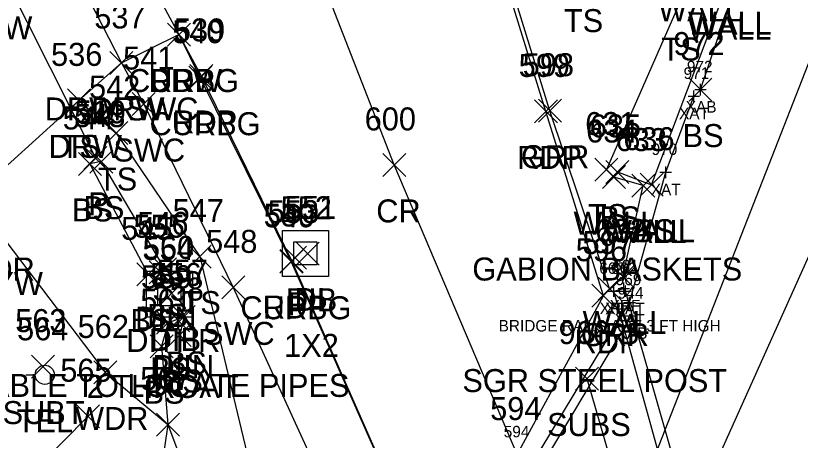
# Model space of a CAD drawing. Extents: x 1764889 to 1767296, y 695936 to 698960.
# Drawn here: x 1766282.3 to 1766350.6, y 696604 to 696640.9 of the extents above; entities that cross this region are included whole.
import ezdxf

# ---------------------------------------------------------------- set-up
doc = ezdxf.new("R2010")
doc.units = 0
for name, color, linetype in [('B_A', 7, 'Continuous'), ('B_C', 7, 'Continuous'), ('B_I', 7, 'Continuous'), ('B_TIC', 7, 'Continuous'), ('BF', 7, 'Continuous'), ('BR', 7, 'Continuous'), ('BSUBM', 7, 'Continuous'), ('D_A', 7, 'Continuous'), ('D_C', 7, 'Continuous'), ('D_I', 7, 'Continuous'), ('D_TIC', 7, 'Continuous'), ('DCP', 7, 'Continuous'), ('DS', 7, 'Continuous'), ('L_A', 7, 'Continuous'), ('L_C', 7, 'Continuous'), ('L_I', 7, 'Continuous'), ('L_TIC', 7, 'Continuous'), ('LAWA', 7, 'Continuous'), ('LELB', 7, 'Continuous'), ('LW', 7, 'Continuous'), ('P_A', 7, 'Continuous'), ('P_I', 7, 'Continuous'), ('P_TIC', 7, 'Continuous'), ('PET', 7, 'Continuous'), ('PRC', 7, 'Continuous'), ('R_A', 7, 'Continuous'), ('R_C', 7, 'Continuous'), ('R_I', 7, 'Continuous'), ('R_TIC', 7, 'Continuous'), ('RC', 7, 'Continuous'), ('RDW', 7, 'Continuous'), ('RGR', 7, 'Continuous'), ('RR', 7, 'Continuous'), ('RSW', 7, 'Continuous'), ('U_A', 7, 'Continuous'), ('U_I', 7, 'Continuous'), ('U_TIC', 7, 'Continuous'), ('UP', 7, 'Continuous'), ('USA', 7, 'Continuous')]:
    doc.layers.add(name, color=color, linetype=linetype)

msp = doc.modelspace()

# ---------------------------------------------------------------- linework, layer by layer
at = {"layer": 'B_TIC'}
for p, q in [((1766341.321, 696633.937), (1766341.396, 696633.937)), ((1766341.893, 696634.509), (1766341.968, 696634.509)), ((1766338.864, 696627.321), (1766338.94, 696627.321)), ((1766334.363, 696616.985), (1766334.438, 696616.985)), ((1766335.228, 696617.225), (1766335.303, 696617.225)), ((1766335.355, 696616.974), (1766335.431, 696616.974)), ((1766335.728, 696615.999), (1766335.803, 696615.999)), ((1766335.881, 696614.829), (1766335.956, 696614.829))]:
    msp.add_line(p, q, dxfattribs=at)
for points in [[(1766341.89, 696634.009), (1766341.89, 696635.009)], [(1766340.817, 696633.937), (1766341.817, 696633.937)], [(1766341.317, 696633.437), (1766341.317, 696634.437)], [(1766341.39, 696634.509), (1766342.39, 696634.509)], [(1766338.861, 696626.821), (1766338.861, 696627.821)], [(1766338.361, 696627.321), (1766339.361, 696627.321)], [(1766334.359, 696616.485), (1766334.359, 696617.485)], [(1766335.224, 696616.725), (1766335.224, 696617.725)], [(1766335.352, 696616.474), (1766335.352, 696617.474)], [(1766333.859, 696616.985), (1766334.859, 696616.985)], [(1766334.724, 696617.225), (1766335.724, 696617.225)], [(1766334.852, 696616.974), (1766335.852, 696616.974)], [(1766335.724, 696615.499), (1766335.724, 696616.499)], [(1766335.224, 696615.999), (1766336.224, 696615.999)], [(1766335.377, 696614.829), (1766336.377, 696614.829)], [(1766335.877, 696614.329), (1766335.877, 696615.329)]]:
    msp.add_lwpolyline(points, dxfattribs=at)
at = {"layer": 'BF'}
msp.add_lwpolyline([(1766346.637, 696577.566), (1766335.352, 696616.974)], dxfattribs=at)
at = {"layer": 'BR'}
msp.add_lwpolyline([(1766346.481, 696577.209), (1766345.386, 696577.081), (1766334.359, 696616.985), (1766335.224, 696617.225)], dxfattribs=at)
at = {"layer": 'BSUBM'}
for points in [[(1766308.079, 696576.128), (1766314.595, 696582.871), (1766317.47, 696585.8), (1766335.724, 696615.999), (1766338.861, 696627.321), (1766341.317, 696633.937)], [(1766301.191, 696567.632), (1766308.317, 696574.421), (1766317.361, 696583.898), (1766335.877, 696614.829)]]:
    msp.add_lwpolyline(points, dxfattribs=at)
at = {"layer": 'D_TIC'}
for points in [[(1766288.247, 696627.574), (1766290.247, 696629.574)], [(1766290.247, 696627.574), (1766288.247, 696629.574)], [(1766305.599, 696618.893), (1766307.599, 696620.893)], [(1766307.599, 696618.893), (1766305.599, 696620.893)], [(1766306.725, 696619.238), (1766308.725, 696621.238)], [(1766308.725, 696619.238), (1766306.725, 696621.238)], [(1766293.926, 696617.632), (1766295.926, 696619.632)], [(1766295.926, 696617.632), (1766293.926, 696619.632)], [(1766294.877, 696615.785), (1766296.877, 696617.785)], [(1766296.877, 696615.785), (1766294.877, 696617.785)], [(1766295.448, 696613.438), (1766297.448, 696615.438)], [(1766297.448, 696613.438), (1766295.448, 696615.438)]]:
    msp.add_lwpolyline(points, dxfattribs=at)
at = {"layer": 'DCP'}
msp.add_lwpolyline([(1766277.33, 696652.193), (1766289.247, 696628.574)], dxfattribs=at)
at = {"layer": 'DS'}
for p, q in [((1766305.518, 696622.266), (1766309.518, 696622.266)), ((1766305.518, 696618.266), (1766305.518, 696622.266)), ((1766309.518, 696622.266), (1766309.518, 696618.266)), ((1766306.518, 696619.266), (1766306.518, 696621.266)), ((1766306.518, 696621.266), (1766308.518, 696621.266)), ((1766308.518, 696621.266), (1766308.518, 696619.266)), ((1766307.523, 696620.268), (1766307.523, 696620.268)), ((1766307.523, 696620.268), (1766307.523, 696620.268)), ((1766308.518, 696619.266), (1766306.518, 696619.266)), ((1766293.687, 696618.718), (1766297.687, 696618.718)), ((1766293.687, 696614.718), (1766293.698, 696618.718)), ((1766297.687, 696618.718), (1766297.687, 696614.718)), ((1766309.518, 696618.266), (1766305.518, 696618.266)), ((1766294.687, 696617.718), (1766296.687, 696617.718)), ((1766294.687, 696615.718), (1766294.687, 696617.718)), ((1766296.687, 696617.718), (1766296.687, 696615.718)), ((1766295.69, 696616.728), (1766295.69, 696616.728)), ((1766296.687, 696615.718), (1766294.687, 696615.718)), ((1766297.687, 696614.718), (1766293.687, 696614.718)), ((1766296.187, 696614.718), (1766296.687, 696614.718))]:
    msp.add_line(p, q, dxfattribs=at)
at = {"layer": 'L_TIC'}
for points in [[(1766340.89, 696633.509), (1766342.89, 696635.509)], [(1766342.89, 696633.509), (1766340.89, 696635.509)], [(1766286.808, 696632.57), (1766288.808, 696634.57)], [(1766288.808, 696632.57), (1766286.808, 696634.57)], [(1766290.058, 696629.732), (1766292.058, 696631.732)], [(1766292.058, 696629.732), (1766290.058, 696631.732)], [(1766288.761, 696627.242), (1766290.761, 696629.242)], [(1766290.761, 696627.242), (1766288.761, 696629.242)], [(1766288.761, 696627.242), (1766290.761, 696629.242)], [(1766290.761, 696627.242), (1766288.761, 696629.242)], [(1766287.766, 696627.042), (1766289.766, 696629.042)], [(1766289.766, 696627.042), (1766287.766, 696629.042)], [(1766332.7, 696626.552), (1766334.7, 696628.552)], [(1766334.7, 696626.552), (1766332.7, 696628.552)], [(1766333.354, 696625.906), (1766335.354, 696627.906)], [(1766335.354, 696625.906), (1766333.354, 696627.906)], [(1766333.667, 696626.353), (1766335.667, 696628.353)], [(1766335.667, 696626.353), (1766333.667, 696628.353)], [(1766335.915, 696625.159), (1766337.915, 696627.159)], [(1766337.915, 696625.159), (1766335.915, 696627.159)], [(1766336.638, 696625.24), (1766338.638, 696627.24)], [(1766338.638, 696625.24), (1766336.638, 696627.24)], [(1766336.638, 696625.24), (1766338.638, 696627.24)], [(1766338.638, 696625.24), (1766336.638, 696627.24)], [(1766297.329, 696618.987), (1766299.329, 696620.987)], [(1766299.329, 696618.987), (1766297.329, 696620.987)], [(1766294.302, 696617.879), (1766296.302, 696619.879)], [(1766296.302, 696617.879), (1766294.302, 696619.879)], [(1766294.302, 696617.879), (1766296.302, 696619.879)], [(1766296.302, 696617.879), (1766294.302, 696619.879)], [(1766292.85, 696617.442), (1766294.85, 696619.442)], [(1766294.85, 696617.442), (1766292.85, 696619.442)], [(1766334.145, 696617.255), (1766336.145, 696619.255)], [(1766336.145, 696617.255), (1766334.145, 696619.255)], [(1766295.934, 696613.732), (1766297.934, 696615.732)], [(1766297.934, 696613.732), (1766295.934, 696615.732)], [(1766295.934, 696613.732), (1766297.934, 696615.732)], [(1766297.934, 696613.732), (1766295.934, 696615.732)], [(1766294.574, 696613.228), (1766296.574, 696615.228)], [(1766296.574, 696613.228), (1766294.574, 696615.228)], [(1766294.574, 696613.228), (1766296.574, 696615.228)], [(1766296.574, 696613.228), (1766294.574, 696615.228)], [(1766295.582, 696612.164), (1766297.582, 696614.164)], [(1766297.582, 696612.164), (1766295.582, 696614.164)], [(1766294, 696611.196), (1766296, 696613.196)], [(1766296, 696611.196), (1766294, 696613.196)], [(1766289.113, 696608.911), (1766291.113, 696610.911)], [(1766291.113, 696608.911), (1766289.113, 696610.911)], [(1766287.604, 696605.107), (1766289.604, 696607.107)], [(1766289.604, 696605.107), (1766287.604, 696607.107)], [(1766294.555, 696604.374), (1766296.555, 696606.374)], [(1766296.555, 696604.374), (1766294.555, 696606.374)], [(1766294.555, 696604.374), (1766296.555, 696606.374)], [(1766296.555, 696604.374), (1766294.555, 696606.374)]]:
    msp.add_lwpolyline(points, dxfattribs=at)
at = {"layer": 'LAWA'}
msp.add_lwpolyline([(1766267.506, 696602.037), (1766280.23, 696622.903), (1766290.113, 696609.911), (1766295.555, 696605.374), (1766300.13, 696593.204), (1766307.624, 696581.45)], dxfattribs=at)
at = {"layer": 'LELB'}
for points in [[(1766329.245, 696716.312), (1766323.358, 696694.495), (1766321.92, 696674.735), (1766323.815, 696657.808), (1766331.595, 696644.505), (1766340.076, 696642.034), (1766333.7, 696627.552)], [(1766311.883, 696556.718), (1766333.813, 696592.111), (1766361.339, 696662.502)], [(1766341.89, 696634.509), (1766349.453, 696656.955)], [(1766287.808, 696633.57), (1766291.058, 696630.732), (1766298.329, 696619.987), (1766303.91, 696596.744)], [(1766289.761, 696628.242), (1766288.766, 696628.042), (1766293.85, 696618.442), (1766295.302, 696618.879)], [(1766289.761, 696628.242), (1766295.302, 696618.879)], [(1766334.667, 696627.353), (1766337.638, 696626.24)], [(1766296.934, 696614.732), (1766296.582, 696613.164), (1766295.574, 696614.228), (1766295, 696612.196), (1766295.555, 696605.374), (1766294.049, 696594.976), (1766286.237, 696589.556)], [(1766296.934, 696614.732), (1766295.574, 696614.228)], [(1766288.604, 696606.107), (1766277.65, 696595.052)]]:
    msp.add_lwpolyline(points, dxfattribs=at)
at = {"layer": 'LW'}
for points in [[(1766337.638, 696626.24), (1766344.295, 696643.864), (1766339.074, 696645.992)], [(1766335.145, 696618.255), (1766336.915, 696626.159), (1766334.354, 696626.906)]]:
    msp.add_lwpolyline(points, dxfattribs=at)
at = {"layer": 'P_TIC'}
for points in [[(1766295.509, 696638.295), (1766297.509, 696640.295)], [(1766297.509, 696638.295), (1766295.509, 696640.295)], [(1766297.451, 696634.694), (1766299.451, 696636.694)], [(1766299.451, 696634.694), (1766297.451, 696636.694)], [(1766327.44, 696631.608), (1766329.44, 696633.608)], [(1766329.44, 696631.608), (1766327.44, 696633.608)], [(1766314.249, 696626.959), (1766316.249, 696628.959)], [(1766316.249, 696626.959), (1766314.249, 696628.959)], [(1766305.332, 696618.601), (1766307.332, 696620.601)], [(1766307.332, 696618.601), (1766305.332, 696620.601)], [(1766332.449, 696615.586), (1766334.449, 696617.586)], [(1766334.449, 696615.586), (1766332.449, 696617.586)]]:
    msp.add_lwpolyline(points, dxfattribs=at)
at = {"layer": 'PET'}
msp.add_lwpolyline([(1766276.936, 696672.807), (1766287.37, 696656.148), (1766289.173, 696652.924), (1766296.509, 696639.295), (1766298.451, 696635.694), (1766306.332, 696619.601), (1766316.811, 696595.838), (1766317.183, 696595.036), (1766319.043, 696590.186), (1766325.953, 696602.77), (1766333.449, 696616.586), (1766328.44, 696632.608), (1766320.063, 696659.678), (1766317.018, 696672.41), (1766316.957, 696677.586), (1766318.473, 696686.097), (1766325.406, 696717.37)], dxfattribs=at)
at = {"layer": 'PRC'}
msp.add_lwpolyline([(1766325.953, 696602.77), (1766315.249, 696627.959), (1766304.04, 696656.661), (1766299.406, 696665.426), (1766289.014, 696682.239)], dxfattribs=at)
at = {"layer": 'R_TIC'}
for points in [[(1766295.509, 696638.295), (1766297.509, 696640.295)], [(1766297.509, 696638.295), (1766295.509, 696640.295)], [(1766295.509, 696638.295), (1766297.509, 696640.295)], [(1766297.509, 696638.295), (1766295.509, 696640.295)], [(1766290.511, 696635.823), (1766292.511, 696637.823)], [(1766292.511, 696635.823), (1766290.511, 696637.823)], [(1766290.511, 696635.823), (1766292.511, 696637.823)], [(1766292.511, 696635.823), (1766290.511, 696637.823)], [(1766297.375, 696634.542), (1766299.375, 696636.542)], [(1766299.375, 696634.542), (1766297.375, 696636.542)], [(1766286.808, 696632.57), (1766288.808, 696634.57)], [(1766288.808, 696632.57), (1766286.808, 696634.57)], [(1766292.452, 696632.251), (1766294.452, 696634.251)], [(1766294.452, 696632.251), (1766292.452, 696634.251)], [(1766327.785, 696631.674), (1766329.785, 696633.674)], [(1766329.785, 696631.674), (1766327.785, 696633.674)], [(1766305.281, 696618.536), (1766307.281, 696620.536)], [(1766307.281, 696618.536), (1766305.281, 696620.536)], [(1766300.242, 696616.311), (1766302.242, 696618.311)], [(1766302.242, 696616.311), (1766300.242, 696618.311)], [(1766332.985, 696616.205), (1766334.985, 696618.205)], [(1766334.985, 696616.205), (1766332.985, 696618.205)]]:
    msp.add_lwpolyline(points, dxfattribs=at)
at = {"layer": 'RC'}
msp.add_lwpolyline([(1766296.509, 696639.295), (1766298.375, 696635.542), (1766306.281, 696619.536), (1766316.847, 696595.702), (1766316.975, 696595.017)], dxfattribs=at)
at = {"layer": 'RDW'}
msp.add_lwpolyline([(1766265.751, 696603.369), (1766278.134, 696624.8), (1766287.808, 696633.57), (1766291.511, 696636.823), (1766296.509, 696639.295)], dxfattribs=at)
at = {"layer": 'RGR'}
msp.add_lwpolyline([(1766333.985, 696617.205), (1766328.785, 696632.674), (1766320.437, 696659.635), (1766318.356, 696672.234), (1766318.492, 696677.027), (1766319.701, 696685.781), (1766326.65, 696717.107)], dxfattribs=at)
at = {"layer": 'RR'}
msp.add_lwpolyline([(1766414.51, 696927.612), (1766410.629, 696876.833), (1766407.503, 696845.702), (1766404.418, 696820.755), (1766396.985, 696776.652), (1766388.165, 696735.438), (1766377.778, 696694.214), (1766366.704, 696658.729), (1766355.141, 696628.572), (1766340.229, 696595.43), (1766321.371, 696561.379), (1766312.455, 696547.475), (1766299.858, 696528.94)], dxfattribs=at)
at = {"layer": 'RSW'}
msp.add_lwpolyline([(1766272.311, 696669.641), (1766282.288, 696653.761), (1766284.86, 696649.837), (1766291.511, 696636.823), (1766293.452, 696633.251), (1766301.242, 696617.311), (1766311.739, 696594.408), (1766316.333, 696584.793), (1766318.332, 696589.371)], dxfattribs=at)
at = {"layer": 'U_TIC'}
for points in [[(1766283.677, 696609.422), (1766285.677, 696611.422)], [(1766285.677, 696609.422), (1766283.677, 696611.422)], [(1766331.008, 696608.38), (1766333.008, 696610.38)], [(1766333.008, 696608.38), (1766331.008, 696610.38)]]:
    msp.add_lwpolyline(points, dxfattribs=at)
at = {"layer": 'UP'}
for p, q in [((1766283.184, 696609.701), (1766284.01, 696609.701)), ((1766284.844, 696609.707), (1766284.844, 696609.707)), ((1766286.51, 696609.707), (1766285.677, 696609.707)), ((1766285.677, 696609.707), (1766285.677, 696609.707)), ((1766286.51, 696609.707), (1766286.51, 696609.707))]:
    msp.add_line(p, q, dxfattribs=at)
msp.add_circle((1766284.844, 696609.707), 0.833, dxfattribs=at)
at = {"layer": 'USA'}
msp.add_lwpolyline([(1766332.008, 696609.38), (1766342.469, 696573.156)], dxfattribs=at)

# ---------------------------------------------------------------- texts
at = {"layer": 'B_A'}
for s, p in [('XAB', (1766340.61, 696632.509)), ('XAT', (1766340.022, 696631.937)), ('XAT', (1766337.565, 696625.321)), ('XRF', (1766333.984, 696615.225)), ('XRF', (1766333.119, 696614.985)), ('XFAT', (1766333.608, 696614.974)), ('XAT', (1766334.429, 696613.999)), ('XAB', (1766334.598, 696612.829))]:
    msp.add_text(s, height=1, dxfattribs=at).set_placement(p)
at = {"layer": 'B_C'}
msp.add_text('BRIDGE RAILS ARE 3 FT HIGH', height=1, dxfattribs=at).set_placement((1766324.328, 696613.474))
at = {"layer": 'B_I'}
for s, p in [('972', (1766340.708, 696636.009)), ('971', (1766340.42, 696635.437)), ('970', (1766337.636, 696628.821)), ('661', (1766334.279, 696618.725)), ('660', (1766333.087, 696618.485)), ('662', (1766334.123, 696618.474)), ('969', (1766334.516, 696617.499)), ('944', (1766334.696, 696616.329)), ('594', (1766324.772, 696604.27))]:
    msp.add_text(s, height=1, dxfattribs=at).set_placement(p)
at = {"layer": 'D_A'}
for s, p in [('P', (1766288.625, 696623.574)), ('DIB', (1766305.827, 696615.238)), ('P', (1766305.977, 696614.893)), ('DI', (1766306.578, 696615.268)), ('DIIN', (1766292.698, 696613.632)), ('DITHR', (1766291.934, 696611.696)), ('DIB', (1766293.979, 696611.785)), ('DIIN', (1766294.22, 696609.438))]:
    msp.add_text(s, height=2, dxfattribs=at).set_placement(p)
at = {"layer": 'D_C'}
for s, p in [('1X2', (1766305.665, 696611.268)), ('UNABLE TO LOCATE PIPES', (1766276.129, 696607.785)), ('2 THROAT', (1766288.486, 696607.696))]:
    msp.add_text(s, height=2, dxfattribs=at).set_placement(p)
at = {"layer": 'D_I'}
for s, p in [('519', (1766287.444, 696631.574)), ('552', (1766305.363, 696623.238)), ('551', (1766305.728, 696623.268)), ('553', (1766304.237, 696622.893)), ('555', (1766292.564, 696621.632)), ('554', (1766293.344, 696619.696)), ('560', (1766293.381, 696619.785)), ('556', (1766294.031, 696617.438))]:
    msp.add_text(s, height=2, dxfattribs=at).set_placement(p)
at = {"layer": 'L_A'}
for s, p in [('WALL', (1766338.203, 696640.432)), ('TS', (1766330.004, 696639.505)), ('WALL', (1766340.783, 696638.864)), ('WALL', (1766340.803, 696639.296)), ('TS', (1766338.486, 696637.034)), ('BS', (1766340.33, 696629.509)), ('TS', (1766286.217, 696628.57)), ('TS', (1766289.468, 696625.732)), ('BS', (1766287.207, 696623.042)), ('BS', (1766288.202, 696623.242)), ('BS', (1766288.202, 696623.242)), ('TS', (1766332.11, 696622.552)), ('BS', (1766333.108, 696622.353)), ('WALL', (1766330.842, 696621.906)), ('WALL', (1766333.403, 696621.159)), ('WALL', (1766334.126, 696621.24)), ('BS', (1766336.079, 696621.24)), ('WDR', (1766277.592, 696617.903)), ('TS', (1766296.738, 696614.987)), ('BS', (1766292.291, 696613.442)), ('BS', (1766293.743, 696613.879)), ('BS', (1766293.743, 696613.879)), ('WALL', (1766331.633, 696613.255)), ('BS', (1766295.375, 696609.732)), ('BS', (1766295.375, 696609.732)), ('BS', (1766294.015, 696609.228)), ('BS', (1766294.015, 696609.228)), ('BS', (1766295.023, 696608.164)), ('BS', (1766293.441, 696607.196)), ('WDR', (1766287.475, 696604.911))]:
    msp.add_text(s, height=2, dxfattribs=at).set_placement(p)
at = {"layer": 'L_C'}
msp.add_text('GABION BASKETS', height=2, dxfattribs=at).set_placement((1766322.039, 696617.906))
at = {"layer": 'L_I'}
for s, p in [('972', (1766339.527, 696637.509)), ('536', (1766285.39, 696636.57)), ('542', (1766288.696, 696633.732)), ('543', (1766287.398, 696631.242)), ('543', (1766287.398, 696631.242)), ('544', (1766286.404, 696631.042)), ('631', (1766331.858, 696630.552)), ('634', (1766331.945, 696629.906)), ('635', (1766332.258, 696630.353)), ('633', (1766334.506, 696629.159)), ('636', (1766335.173, 696629.24)), ('636', (1766335.173, 696629.24)), ('547', (1766295.967, 696622.987)), ('546', (1766292.885, 696621.879)), ('546', (1766292.885, 696621.879)), ('545', (1766291.488, 696621.442)), ('632', (1766332.736, 696621.255)), ('557', (1766294.572, 696617.732)), ('557', (1766294.572, 696617.732)), ('559', (1766293.204, 696617.228)), ('559', (1766293.204, 696617.228)), ('558', (1766294.219, 696616.164)), ('561', (1766293.158, 696615.196)), ('562', (1766287.704, 696612.911)), ('565', (1766286.194, 696609.107)), ('567', (1766293.146, 696608.374)), ('567', (1766293.146, 696608.374))]:
    msp.add_text(s, height=2, dxfattribs=at).set_placement(p)
at = {"layer": 'P_A'}
for s, p in [('RDP', (1766293.997, 696634.295)), ('RDP', (1766295.939, 696630.694)), ('RDP', (1766325.928, 696627.608)), ('CR', (1766313.682, 696622.959)), ('RDP', (1766303.82, 696614.601)), ('RDP', (1766330.937, 696611.586))]:
    msp.add_text(s, height=2, dxfattribs=at).set_placement(p)
at = {"layer": 'P_I'}
for s, p in [('539', (1766296.081, 696638.694)), ('599', (1766326.07, 696635.608)), ('600', (1766312.674, 696630.959)), ('550', (1766303.883, 696622.601)), ('596', (1766331.032, 696619.586)), ('594', (1766323.591, 696605.77)), ('594', (1766323.591, 696605.77))]:
    msp.add_text(s, height=2, dxfattribs=at).set_placement(p)
at = {"layer": 'R_A'}
for s, p in [('DRW', (1766277.375, 696638.877)), ('CURBG', (1766292.091, 696634.295)), ('DRW', (1766293.879, 696634.295)), ('DRW SWC', (1766284.842, 696631.823)), ('DRW', (1766288.881, 696631.823)), ('CURBG', (1766293.958, 696630.542)), ('DRW', (1766285.178, 696628.57)), ('SWC', (1766290.814, 696628.251)), ('GRR', (1766326.273, 696627.674)), ('CURBG', (1766301.864, 696614.536)), ('SWC', (1766298.604, 696612.311)), ('GRR', (1766331.473, 696612.205))]:
    msp.add_text(s, height=2, dxfattribs=at).set_placement(p)
at = {"layer": 'R_C'}
msp.add_text('SGR STEEL POST', height=2, dxfattribs=at).set_placement((1766321.174, 696608.205))
at = {"layer": 'R_I'}
for s, p in [('537', (1766289.149, 696639.823)), ('537', (1766289.149, 696639.823)), ('540', (1766295.926, 696638.542)), ('536', (1766285.39, 696636.57)), ('541', (1766291.656, 696636.251)), ('598', (1766326.423, 696635.674)), ('549', (1766303.911, 696622.536)), ('548', (1766298.88, 696620.311)), ('597', (1766331.623, 696620.205))]:
    msp.add_text(s, height=2, dxfattribs=at).set_placement(p)
at = {"layer": 'U_A'}
for s, p in [('GUYW', (1766276.363, 696616.642)), ('SUBT', (1766281.173, 696605.422)), ('TEL', (1766282.403, 696604.707)), ('SUBS', (1766328.543, 696604.38))]:
    msp.add_text(s, height=2, dxfattribs=at).set_placement(p)
at = {"layer": 'U_I'}
for s, p in [('563', (1766282.267, 696613.422)), ('564', (1766282.434, 696612.707)), ('966', (1766329.543, 696612.38))]:
    msp.add_text(s, height=2, dxfattribs=at).set_placement(p)

doc.saveas('drawing.dxf')
